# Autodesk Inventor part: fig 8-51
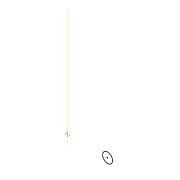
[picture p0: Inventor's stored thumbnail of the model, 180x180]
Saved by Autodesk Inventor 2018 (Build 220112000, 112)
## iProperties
Shininess: 77.0
Length Units: 11269
Angle Units: 11279
Time Units: 11290
Mass Units: 11283
Length Display Precision: 3
Angle Display Precision: 2
Created: 2002-01
Part Number: fig 8-51
Document SubType Name: Modeling
Designer: CADSoft
Density: 1 g/cm^3
Material: Generic
Appearance: Default
Density: 0.0
Volumn: 0.0
Area: 0.0
PropertySet Name: Model Information
Control State: 0
Master: False
Checked Out: False
Author: CADSoft
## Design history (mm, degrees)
sketch "Sketch2"
  geometry: C1 r 2.5 at (-20, -0.092); 1 further point
  constraints: 1 centre point, 2 other
workaxis "Work Axis1"
body "Solid1"
